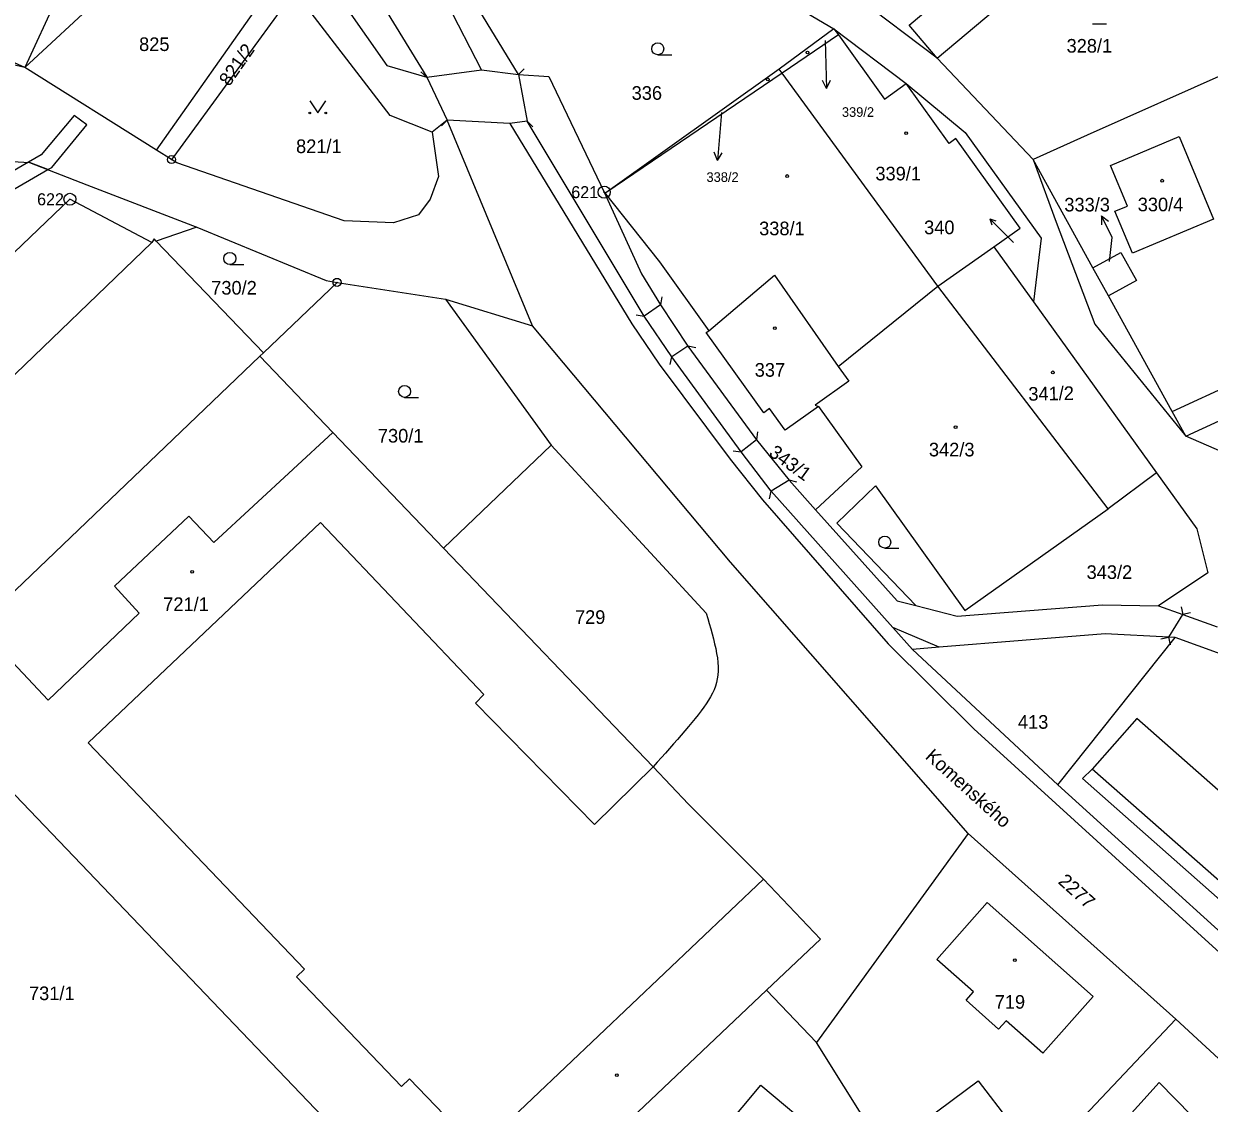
# Model space of a CAD drawing. Extents: x -504988 to -494607, y -1123820 to -1114018.
# Drawn here: x -497144.2 to -496996.2, y -1120483.5 to -1120348.7 of the extents above; entities that cross this region are included whole.
import ezdxf

# ---------------------------------------------------------------- set-up
doc = ezdxf.new("R2010")
doc.units = 0
for name, color, linetype in [('Hranice parcel', 7, 'Continuous'), ('Parcelní čísla', 7, 'Continuous'), ('Pop  PČ popisy', 7, 'Continuous'), ('Vnitřní kresba', 7, 'Continuous'), ('Věcná břemena k části', 7, 'Continuous'), ('Značky bodu BP', 7, 'Continuous'), ('Značky budov', 7, 'Continuous'), ('Značky kultur', 7, 'Continuous')]:
    doc.layers.add(name, color=color, linetype=linetype)

msp = doc.modelspace()

# ---------------------------------------------------------------- linework, layer by layer
at = {"layer": 'Hranice parcel'}
for p, q in [((-497111.25, -1120326.76), (-497093.87, -1120355.42)), ((-497144.01, -1120354.19), (-497120.07, -1120332)), ((-497060.6, -1120339.07), (-497043.04, -1120349.36)), ((-497082.4, -1120355.08), (-497091.53, -1120340.15)), ((-497127.59, -1120364.52), (-497112.04, -1120342.45)), ((-497030.16, -1120353.05), (-497041.82, -1120344.2)), ((-497043.04, -1120349.36), (-497049.88, -1120354.41)), ((-497042.49, -1120350.13), (-497049.52, -1120354.9)), ((-497043.04, -1120349.36), (-497034.01, -1120356.2)), ((-497043.04, -1120349.36), (-497042.49, -1120350.13)), ((-497144.01, -1120354.19), (-497151.53, -1120352.48)), ((-497018.18, -1120365.69), (-497030.16, -1120353.05)), ((-497127.59, -1120364.52), (-497144.01, -1120354.19)), ((-497093.87, -1120355.42), (-497087.04, -1120354.48)), ((-497087.04, -1120354.48), (-497082.4, -1120355.08)), ((-497049.88, -1120354.41), (-497071.53, -1120369.83)), ((-497049.52, -1120354.9), (-497049.88, -1120354.41)), ((-497049.52, -1120354.9), (-497071.53, -1120369.83)), ((-497030.06, -1120381.49), (-497049.52, -1120354.9)), ((-497091.3, -1120360.79), (-497093.2, -1120362.28)), ((-497080.68, -1120386.46), (-497091.3, -1120360.79)), ((-497083.51, -1120361.17), (-497091.3, -1120360.79)), ((-497081.33, -1120360.88), (-497083.51, -1120361.17)), ((-497066.73, -1120385.26), (-497081.33, -1120360.88)), ((-497125.71, -1120365.7), (-497127.59, -1120364.52)), ((-497125.07, -1120366.1), (-497125.71, -1120365.7)), ((-497010.72, -1120379.21), (-497018.18, -1120365.69)), ((-497071.53, -1120369.83), (-497071.72, -1120369.76)), ((-497122.56, -1120374.15), (-497127.62, -1120375.87)), ((-497114.25, -1120389.81), (-497127.62, -1120375.87)), ((-497030.06, -1120381.49), (-497023.07, -1120376.57)), ((-497023.07, -1120376.57), (-497018.14, -1120383.44)), ((-497008.79, -1120382.71), (-497010.72, -1120379.21)), ((-497105.06, -1120381.02), (-497114.25, -1120389.81)), ((-497105.06, -1120381.02), (-497091.52, -1120383.1)), ((-497042.53, -1120391.52), (-497030.06, -1120381.49)), ((-497008.83, -1120409.31), (-497030.06, -1120381.49)), ((-497000.82, -1120397.16), (-497008.79, -1120382.71)), ((-497091.52, -1120383.1), (-497080.68, -1120386.46)), ((-497064.68, -1120383.82), (-497061.28, -1120389)), ((-497018.14, -1120383.44), (-497002.8, -1120404.8)), ((-497063.27, -1120390.31), (-497066.73, -1120385.26)), ((-497000.82, -1120397.16), (-496976.34, -1120385.78)), ((-497114.68, -1120390.22), (-497114.25, -1120389.81)), ((-497061.28, -1120389), (-497052.69, -1120400.67)), ((-496999.13, -1120400.23), (-496974.65, -1120388.84)), ((-497054.63, -1120402.16), (-497063.27, -1120390.31)), ((-497044.98, -1120396.51), (-497039.57, -1120404.05)), ((-496999.13, -1120400.23), (-497000.82, -1120397.16)), ((-497052.69, -1120400.67), (-497048.63, -1120405.72)), ((-497050.86, -1120407.07), (-497054.63, -1120402.16)), ((-497039.57, -1120404.05), (-497045.34, -1120409.4)), ((-497002.8, -1120404.8), (-497008.83, -1120409.31)), ((-497048.63, -1120405.72), (-497045.34, -1120409.4)), ((-497015.12, -1120443.74), (-497000.46, -1120425.36)), ((-497015.12, -1120443.74), (-496980.45, -1120475.17)), ((-497026.3, -1120449.82), (-497045.24, -1120475.9)), ((-497000.39, -1120472.99), (-497026.3, -1120449.82)), ((-497045.24, -1120475.9), (-497051.44, -1120469.37)), ((-496991.45, -1120481.25), (-497000.39, -1120472.99)), ((-497036.74, -1120489.41), (-497045.24, -1120475.9))]:
    msp.add_line(p, q, dxfattribs=at)
for points in [[(-497087.04, -1120354.48), (-497099.88, -1120329.46), (-497105.48, -1120320.32), (-497114.23, -1120310.57), (-497171.4, -1120273.63), (-497183.51, -1120268.01), (-497197.35, -1120264.04), (-497268.56, -1120247.23), (-497277.08, -1120243.87), (-497341.22, -1120209.24)], [(-497030.16, -1120353.05), (-497011.01, -1120336.91), (-497008.04, -1120334.55), (-497008.04, -1120333.54), (-497020.72, -1120317.84)], [(-497114.64, -1120331.35), (-497098.85, -1120353.94), (-497093.87, -1120355.42)], [(-497110.37, -1120344.64), (-497125.43, -1120365.32), (-497125.71, -1120365.7)], [(-497093.2, -1120362.28), (-497098.42, -1120360.2), (-497110.37, -1120344.64)], [(-497082.4, -1120355.08), (-497078.64, -1120355.31), (-497071.72, -1120369.76)], [(-496993.53, -1120354.64), (-497011.43, -1120362.66), (-497018.18, -1120365.69)], [(-497034.01, -1120356.2), (-497026.68, -1120362.32), (-497017.2, -1120375.5), (-497018.14, -1120383.44)], [(-497023.07, -1120376.57), (-497019.82, -1120374.24), (-497027.84, -1120363.08), (-497028.65, -1120363.67), (-497034.01, -1120356.2)], [(-497083.51, -1120361.17), (-497068.27, -1120386.21), (-497064.86, -1120391.23), (-497055.98, -1120403.1), (-497051.98, -1120408.19), (-497036.29, -1120426.16), (-497025.6, -1120436.78), (-496964.64, -1120492.27), (-496902.58, -1120548.07), (-496901.27, -1120546.76)], [(-497093.2, -1120362.28), (-497092.38, -1120367.81), (-497093.43, -1120370.64), (-497094.89, -1120372.61), (-497098.01, -1120373.58), (-497104.16, -1120373.36), (-497125.07, -1120366.1)], [(-496995.68, -1120373.14), (-497005.79, -1120377.37), (-497007.98, -1120372.14), (-497006.41, -1120371.49), (-497008.52, -1120366.45), (-496999.98, -1120362.82), (-496995.68, -1120373.14)], [(-497148.49, -1120365.77), (-497143.45, -1120366.04), (-497136.3, -1120368.85), (-497122.56, -1120374.15)], [(-497138.39, -1120370.65), (-497179.05, -1120409.53), (-497193.58, -1120423.41), (-497172.83, -1120445.25), (-497173.89, -1120446.23), (-497190.59, -1120428.71), (-497201.46, -1120439.14), (-497184.36, -1120457.1)], [(-497127.62, -1120375.87), (-497127.87, -1120375.6), (-497128.17, -1120376.06), (-497138.39, -1120370.65)], [(-497071.72, -1120369.76), (-497064.82, -1120378.47), (-497058.65, -1120387.07)], [(-497071.72, -1120369.76), (-497067.07, -1120379.96), (-497064.68, -1120383.82)], [(-497122.56, -1120374.15), (-497106.41, -1120380.81), (-497105.06, -1120381.02)], [(-497010.72, -1120379.21), (-497007.22, -1120377.28), (-497005.29, -1120380.78), (-497008.79, -1120382.71)], [(-497058.65, -1120387.07), (-497050.47, -1120380.11), (-497042.53, -1120391.52)], [(-497091.52, -1120383.1), (-497078.34, -1120401.33), (-497091.77, -1120414.19)], [(-497026.3, -1120449.82), (-497055.94, -1120415.97), (-497080.68, -1120386.46)], [(-497044.98, -1120396.51), (-497049.13, -1120399.49), (-497051.08, -1120396.78), (-497051.79, -1120397.3), (-497058.97, -1120387.3), (-497058.65, -1120387.07)], [(-497114.68, -1120390.22), (-497148.16, -1120422.27), (-497149.86, -1120423.88), (-497158.04, -1120431.67)], [(-497091.77, -1120414.19), (-497105.6, -1120399.75), (-497114.68, -1120390.22)], [(-497042.53, -1120391.52), (-497041.17, -1120393.36), (-497045.4, -1120396.37), (-497044.98, -1120396.51)], [(-496981.64, -1120405.4), (-496984.42, -1120406.65), (-496999.13, -1120400.23)], [(-497002.8, -1120404.8), (-496997.77, -1120411.81), (-496996.39, -1120417.29), (-497002.55, -1120421.39)], [(-497029.93, -1120426.57), (-497035.69, -1120424.11), (-497050.86, -1120407.07)], [(-497032.82, -1120421.38), (-497042.69, -1120411.07), (-497037.87, -1120406.41)], [(-497037.87, -1120406.41), (-497026.69, -1120421.97), (-497008.83, -1120409.31)], [(-497045.34, -1120409.4), (-497035.14, -1120420.78), (-497032.82, -1120421.38)], [(-497091.77, -1120414.19), (-497065.62, -1120441.49), (-497061.21, -1120446.16), (-497051.82, -1120455.54), (-497044.73, -1120463.01), (-497051.44, -1120469.37)], [(-497032.82, -1120421.38), (-497027.68, -1120422.69), (-497009.52, -1120421.28), (-497002.55, -1120421.39)], [(-497002.55, -1120421.39), (-496999.51, -1120422.48), (-496995.2, -1120424.01)], [(-497000.46, -1120425.36), (-497001.25, -1120425.31), (-497009.18, -1120424.9), (-497029.93, -1120426.57)], [(-496953.48, -1120444.28), (-496957.49, -1120440.67), (-496973.11, -1120435.26), (-497000.46, -1120425.36)], [(-497029.93, -1120426.57), (-497033.22, -1120426.87), (-497015.12, -1120443.74)], [(-497158.04, -1120431.67), (-497099.59, -1120492.76), (-497095.5, -1120496.96), (-497089.26, -1120503.55)], [(-496971.63, -1120465.11), (-497005.26, -1120435.49), (-497010.82, -1120441.8), (-497012.04, -1120442.95), (-496978.4, -1120472.66)], [(-497051.44, -1120469.37), (-497088.42, -1120504.44), (-497089.26, -1120503.55)], [(-497000.39, -1120472.99), (-497012.51, -1120485.88), (-497017.14, -1120491.02)], [(-497059.79, -1120505.34), (-497057.75, -1120507.09), (-497066.7, -1120517.58), (-497067.75, -1120516.57), (-497075.56, -1120525.53), (-497081, -1120520.69), (-497073.41, -1120511.92), (-497075.98, -1120509.69), (-497067.16, -1120499.13), (-497070.05, -1120496.71), (-497067.17, -1120493.26), (-497064.25, -1120495.69), (-497052.18, -1120481.23), (-497044.72, -1120487.47), (-497059.79, -1120505.34)], [(-497036.74, -1120489.41), (-497025.04, -1120480.72), (-497017.14, -1120491.02)]]:
    msp.add_lwpolyline(points, dxfattribs=at)
at = {"layer": 'Pop  PČ popisy'}
for p, q in [((-497044.15, -1120350.82), (-497044.06, -1120353.81)), ((-497044.06, -1120353.81), (-497043.96, -1120356.81)), ((-497043.96, -1120356.81), (-497044.49, -1120355.83)), ((-497043.96, -1120356.81), (-497043.49, -1120355.79)), ((-497057.08, -1120359.81), (-497057.31, -1120362.8)), ((-497057.31, -1120362.8), (-497057.57, -1120365.79)), ((-497057.57, -1120365.79), (-497057.98, -1120364.75)), ((-497057.57, -1120365.79), (-497056.98, -1120364.84)), ((-497022.11, -1120374.57), (-497023.6, -1120373.08)), ((-497023.6, -1120373.08), (-497022.85, -1120373.33)), ((-497023.6, -1120373.08), (-497023.35, -1120373.83)), ((-497009.66, -1120372.71), (-497009.67, -1120373.83)), ((-497008.34, -1120375.41), (-497009.66, -1120372.71)), ((-497009.66, -1120372.71), (-497008.77, -1120373.39)), ((-497020.63, -1120376.06), (-497022.11, -1120374.57)), ((-497008.64, -1120378.4), (-497008.34, -1120375.41))]:
    msp.add_line(p, q, dxfattribs=at)
at = {"layer": 'Vnitřní kresba'}
for p, q in [((-497033.66, -1120348.9), (-497014.51, -1120332.75)), ((-497135.23, -1120335.13), (-497144.01, -1120354.19)), ((-497042.49, -1120350.13), (-497036.73, -1120358.15)), ((-497030.16, -1120353.05), (-497033.66, -1120348.9)), ((-497144.01, -1120354.19), (-497150.86, -1120351.16)), ((-497081.72, -1120354.35), (-497082.4, -1120355.08)), ((-497094.6, -1120354.74), (-497093.87, -1120355.42)), ((-497093.87, -1120355.42), (-497091.3, -1120360.79)), ((-497082.4, -1120355.08), (-497081.33, -1120360.88)), ((-497036.73, -1120358.15), (-497034.01, -1120356.2)), ((-497092.02, -1120361.49), (-497091.3, -1120360.79)), ((-497080.64, -1120361.6), (-497081.33, -1120360.88)), ((-497018.18, -1120365.69), (-497015.31, -1120373.52)), ((-497015.31, -1120373.52), (-497010.5, -1120386.24)), ((-497128.17, -1120376.06), (-497163.17, -1120409.74)), ((-497064.68, -1120383.82), (-497066.73, -1120385.26)), ((-497064.51, -1120382.83), (-497064.68, -1120383.82)), ((-497067.72, -1120385.09), (-497066.73, -1120385.26)), ((-497010.5, -1120386.24), (-496999.13, -1120400.23)), ((-497061.28, -1120389), (-497063.27, -1120390.31)), ((-497060.3, -1120389.21), (-497061.28, -1120389)), ((-497063.48, -1120391.29), (-497063.27, -1120390.31)), ((-497120.42, -1120413.49), (-497105.6, -1120399.75)), ((-497052.57, -1120399.68), (-497052.69, -1120400.67)), ((-497078.34, -1120401.33), (-497058.99, -1120422.33)), ((-497052.69, -1120400.67), (-497054.63, -1120402.16)), ((-497055.62, -1120402.04), (-497054.63, -1120402.16)), ((-497048.63, -1120405.72), (-497050.86, -1120407.07)), ((-497047.66, -1120405.96), (-497048.63, -1120405.72)), ((-497051.1, -1120408.04), (-497050.86, -1120407.07)), ((-497132.83, -1120418.97), (-497123.57, -1120410.21)), ((-497123.57, -1120410.21), (-497120.42, -1120413.49)), ((-497107.12, -1120411.01), (-497136.12, -1120438.51)), ((-497086.72, -1120432.46), (-497107.12, -1120411.01)), ((-497129.76, -1120422.32), (-497132.83, -1120418.97)), ((-497141.11, -1120433.17), (-497129.76, -1120422.32)), ((-497001.25, -1120425.31), (-496999.51, -1120422.48)), ((-496999.73, -1120421.51), (-496999.51, -1120422.48)), ((-496998.54, -1120422.26), (-496999.51, -1120422.48)), ((-497149.86, -1120423.88), (-497141.11, -1120433.17)), ((-497035.69, -1120424.11), (-497033.22, -1120426.87)), ((-497002.23, -1120425.53), (-497001.25, -1120425.31)), ((-497001.03, -1120426.28), (-497001.25, -1120425.31)), ((-497087.78, -1120433.54), (-497086.72, -1120432.46)), ((-497072.92, -1120448.7), (-497087.78, -1120433.54)), ((-497136.12, -1120438.51), (-497109.11, -1120466.75)), ((-497065.62, -1120441.49), (-497072.92, -1120448.7)), ((-496977.18, -1120471.43), (-497010.82, -1120441.8)), ((-497095.5, -1120496.96), (-497051.82, -1120455.54)), ((-497030.21, -1120465.54), (-497023.92, -1120458.44)), ((-497023.92, -1120458.44), (-497010.7, -1120470.16)), ((-497025.62, -1120469.6), (-497030.21, -1120465.54)), ((-497109.11, -1120466.75), (-497110.13, -1120467.71)), ((-497110.13, -1120467.71), (-497097.03, -1120481.41)), ((-497026.55, -1120470.65), (-497025.62, -1120469.6)), ((-497022.49, -1120474.25), (-497026.55, -1120470.65)), ((-497010.7, -1120470.16), (-497016.99, -1120477.26)), ((-497021.56, -1120473.21), (-497022.49, -1120474.25)), ((-497016.99, -1120477.26), (-497021.56, -1120473.21)), ((-497097.03, -1120481.41), (-497096.02, -1120480.44)), ((-497096.02, -1120480.44), (-497091.7, -1120484.96)), ((-497009.44, -1120488.65), (-497002.46, -1120480.91)), ((-497002.46, -1120480.91), (-496998.4, -1120485.05))]:
    msp.add_line(p, q, dxfattribs=at)
msp.add_lwpolyline([(-497058.99, -1120422.33), (-497058.8, -1120422.97), (-497058.6, -1120423.62), (-497058.42, -1120424.26), (-497058.24, -1120424.89), (-497058.08, -1120425.52), (-497057.93, -1120426.14), (-497057.79, -1120426.74), (-497057.68, -1120427.34), (-497057.59, -1120427.91), (-497057.53, -1120428.47), (-497057.5, -1120429.02), (-497057.5, -1120429.54), (-497057.53, -1120430.04), (-497057.6, -1120430.53), (-497057.71, -1120430.99), (-497057.84, -1120431.44), (-497058.01, -1120431.89), (-497058.21, -1120432.32), (-497058.43, -1120432.76), (-497058.69, -1120433.2), (-497058.97, -1120433.63), (-497059.28, -1120434.07), (-497059.62, -1120434.53), (-497059.98, -1120435), (-497060.36, -1120435.48), (-497060.77, -1120435.98), (-497061.2, -1120436.49), (-497061.64, -1120437.02), (-497062.11, -1120437.56), (-497062.58, -1120438.1), (-497063.07, -1120438.65), (-497063.57, -1120439.21), (-497064.08, -1120439.78), (-497064.58, -1120440.34), (-497065.1, -1120440.92), (-497065.62, -1120441.49)], dxfattribs=at)
at = {"layer": 'Věcná břemena k části'}
for points in [[(-497141.97, -1120365.11), (-497143.58, -1120366.03), (-497143.45, -1120366.04), (-497141.14, -1120366.95), (-497140.65, -1120366.67), (-497136.27, -1120361.36), (-497137.88, -1120360.17)], [(-497143.58, -1120366.03), (-497149.06, -1120369.18), (-497175.17, -1120394.16), (-497180.6, -1120400.15), (-497191.82, -1120413.77), (-497194.14, -1120417.36), (-497195.46, -1120419.77), (-497196.07, -1120422.19), (-497190.89, -1120433.77), (-497183.15, -1120447.29), (-497179.76, -1120452.65), (-497178.29, -1120451.23), (-497181.43, -1120446.25), (-497189.11, -1120432.87), (-497193.97, -1120422.01), (-497193.6, -1120420.55), (-497190.18, -1120414.93), (-497179.08, -1120401.45), (-497173.71, -1120395.52), (-497167.11, -1120388.63), (-497147.86, -1120370.8), (-497141.14, -1120366.95), (-497143.45, -1120366.04)]]:
    msp.add_lwpolyline(points, close=True, dxfattribs=at)
at = {"layer": 'Značky bodu BP'}
for centre, radius in [((-497125.71, -1120365.7), 0.5), ((-497125.71, -1120365.7), 0.0303), ((-497071.72, -1120369.76), 0.75), ((-497138.39, -1120370.65), 0.75), ((-497138.39, -1120370.65), 0.03), ((-497071.72, -1120369.76), 0.03), ((-497105.06, -1120381.02), 0.5), ((-497105.06, -1120381.02), 0.0303)]:
    msp.add_circle(centre, radius, dxfattribs=at)
at = {"layer": 'Značky budov'}
for centre in [(-497046.35, -1120352.32), (-497051.29, -1120355.68), (-497034.04, -1120362.39), (-497048.89, -1120367.75), (-497002.07, -1120368.33), (-497050.42, -1120386.75), (-497015.72, -1120392.26), (-497027.86, -1120399.09), (-497123.14, -1120417.16), (-497020.46, -1120465.65), (-497070.13, -1120479.99)]:
    msp.add_circle(centre, 0.175, dxfattribs=at)
at = {"layer": 'Značky kultur'}
for p, q in [((-497010.79, -1120348.73), (-497009.04, -1120348.73)), ((-497065.03, -1120352.61), (-497063.28, -1120352.61)), ((-497118.44, -1120378.79), (-497116.69, -1120378.79)), ((-497096.62, -1120395.38), (-497094.87, -1120395.38)), ((-497036.7, -1120414.2), (-497034.95, -1120414.2))]:
    msp.add_line(p, q, dxfattribs=at)
msp.add_lwpolyline([(-497108.46, -1120358.37), (-497107.46, -1120359.87), (-497106.46, -1120358.37)], dxfattribs=at)
for centre, radius in [((-497065.03, -1120351.86), 0.75), ((-497108.46, -1120359.87), 0.1), ((-497106.46, -1120359.87), 0.1), ((-497118.44, -1120378.04), 0.75), ((-497096.62, -1120394.63), 0.75), ((-497036.7, -1120413.45), 0.75)]:
    msp.add_circle(centre, radius, dxfattribs=at)

# ---------------------------------------------------------------- texts
at = {"layer": 'Parcelní čísla'}
for s, height, p in [('825', 1.7, (-497129.76, -1120352.14)), ('328/1', 1.7, (-497014.01, -1120352.34)), ('336', 1.7, (-497068.29, -1120358.23)), ('339/2', 1.2, (-497042.05, -1120360.36)), ('821/1', 1.7, (-497110.17, -1120364.88)), ('338/2', 1.2, (-497058.95, -1120368.48)), ('339/1', 1.7, (-497037.87, -1120368.29)), ('333/3', 1.7, (-497014.29, -1120372.17)), ('330/4', 1.7, (-497005.13, -1120372.15)), ('338/1', 1.7, (-497052.38, -1120375.14)), ('340', 1.7, (-497031.79, -1120375.01)), ('730/2', 1.7, (-497120.76, -1120382.55)), ('337', 1.7, (-497052.93, -1120392.8)), ('730/1', 1.7, (-497099.96, -1120401.02)), ('342/3', 1.7, (-497031.19, -1120402.75)), ('343/2', 1.7, (-497011.51, -1120418.05)), ('721/1', 1.7, (-497126.75, -1120422.05)), ('729', 1.7, (-497075.36, -1120423.66)), ('413', 1.7, (-497020.08, -1120436.75)), ('731/1', 1.7, (-497143.5, -1120470.63)), ('719', 1.7, (-497022.98, -1120471.7))]:
    msp.add_text(s, height=height, dxfattribs=at).set_placement(p)
for s, rotation, p in [('821/2', 55, (-497118.52, -1120356.65)), ('341/2', 1, (-497018.77, -1120395.8)), ('343/1', 324, (-497051.29, -1120402.57)), ('2277', 318, (-497015.18, -1120455.96))]:
    msp.add_text(s, height=1.7, rotation=rotation, dxfattribs=at).set_placement(p)
at = {"layer": 'Pop  PČ popisy'}
msp.add_text('Komenského', height=1.7, rotation=318, dxfattribs=at).set_placement((-497031.75, -1120440.37))
at = {"layer": 'Značky bodu BP'}
for s, p in [('621', (-497075.82, -1120370.51)), ('622', (-497142.49, -1120371.4))]:
    msp.add_text(s, height=1.5, dxfattribs=at).set_placement(p)

doc.saveas('drawing.dxf')
